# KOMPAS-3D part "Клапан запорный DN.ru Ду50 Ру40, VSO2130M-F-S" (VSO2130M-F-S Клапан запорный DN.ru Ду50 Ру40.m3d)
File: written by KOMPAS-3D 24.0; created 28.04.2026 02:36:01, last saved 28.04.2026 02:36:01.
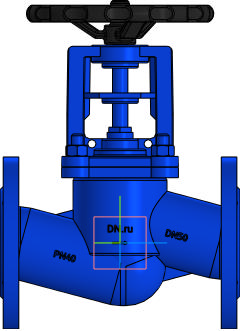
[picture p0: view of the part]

Document properties: Автор: DN.ru; Полное имя файла: C:\Работа\ГОТОВЫЕ ИСХОДНИКИ\VSO2130M-F-S Клапан запорный сильфонный DN.ru Ду15-100 Ру40\DN50\VSO2130M-F-S Клапан запорный DN.ru Ду50 Ру40.m3d

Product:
- Part/product: Клапан запорный DN.ru Ду50 Ру40  | designation VSO2130M-F-S
    Масса: 12
    Раздел спецификации: Прочие изделия
    Примечание: D090-01975

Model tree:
1. Операция без истории:1

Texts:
  VSO2130M-F-S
